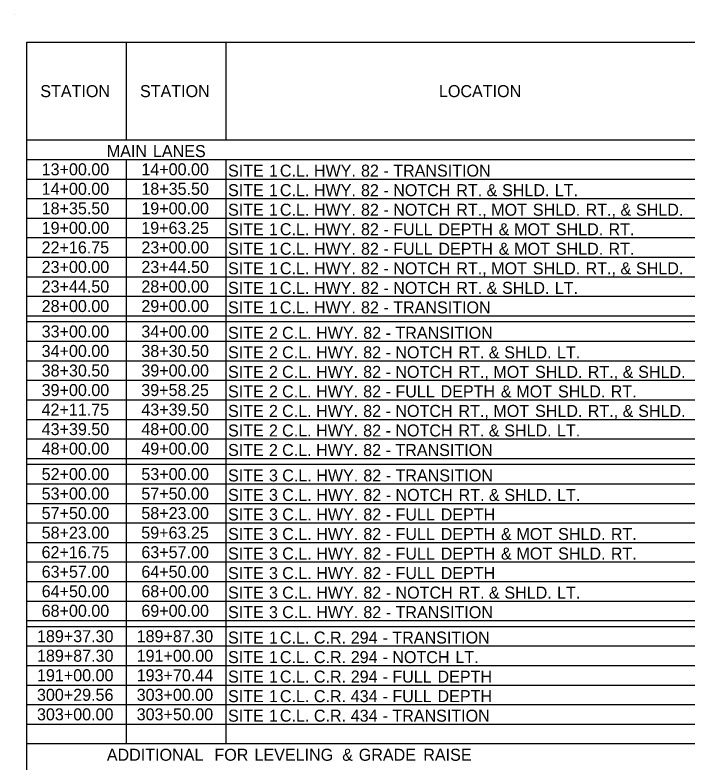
# Model space of a CAD drawing. Extents: x 977434 to 989596, y 1525697 to 1528336.
# Drawn here: x 982700.1 to 982968.2, y 1527813.7 to 1528112 of the extents above; entities that cross this region are included whole.
import ezdxf

# ---------------------------------------------------------------- set-up
doc = ezdxf.new("R2010")
doc.units = 0
doc.layers.add('Default', color=7, linetype='Continuous')
doc.layers.add('R_Border Prem', color=7, linetype='Continuous')

msp = doc.modelspace()

# ---------------------------------------------------------------- linework, layer by layer
at = {"layer": 'Default'}
for p, q in [((982704.74, 1528101.06), (984062.72, 1528101.06)), ((982704.74, 1527610.44), (982704.74, 1528101.06)), ((982704.74, 1527610.44), (982704.74, 1528101.06)), ((982744.52, 1528062.06), (982744.52, 1528101.06)), ((982784.3, 1528062.06), (982784.3, 1528101.06)), ((982704.74, 1528062.06), (984062.72, 1528062.06)), ((982704.74, 1528054.26), (984062.72, 1528054.26)), ((982744.52, 1527821.04), (982744.52, 1528054.26)), ((982744.52, 1527821.04), (982744.52, 1528054.26)), ((982784.3, 1527821.04), (982784.3, 1528054.26)), ((982784.3, 1527821.04), (982784.3, 1528054.26)), ((982704.74, 1528046.46), (984062.72, 1528046.46)), ((982704.74, 1528038.66), (984062.72, 1528038.66)), ((982704.74, 1528030.86), (984062.72, 1528030.86)), ((982704.74, 1528023.06), (984062.72, 1528023.06)), ((982704.74, 1528015.26), (984062.72, 1528015.26)), ((982704.74, 1528007.46), (984062.72, 1528007.46)), ((982704.74, 1527999.66), (984062.72, 1527999.66)), ((982704.74, 1527991.86), (984062.72, 1527991.86)), ((982704.74, 1527989.52), (984062.72, 1527989.52)), ((982704.74, 1527981.72), (984062.72, 1527981.72)), ((982704.74, 1527973.92), (984062.72, 1527973.92)), ((982704.74, 1527966.12), (984062.72, 1527966.12)), ((982704.74, 1527958.32), (984062.72, 1527958.32)), ((982704.74, 1527950.52), (984062.72, 1527950.52)), ((982704.74, 1527942.72), (984062.72, 1527942.72)), ((982704.74, 1527934.92), (984062.72, 1527934.92)), ((982704.74, 1527932.58), (984062.72, 1527932.58)), ((982704.74, 1527924.78), (984062.72, 1527924.78)), ((982704.74, 1527916.98), (984062.72, 1527916.98)), ((982704.74, 1527909.18), (984062.72, 1527909.18)), ((982704.74, 1527901.38), (984062.72, 1527901.38)), ((982704.74, 1527893.58), (984062.72, 1527893.58)), ((982704.74, 1527885.78), (984062.72, 1527885.78)), ((982704.74, 1527877.98), (984062.72, 1527877.98)), ((982704.74, 1527870.18), (984062.72, 1527870.18)), ((982704.74, 1527867.84), (984062.72, 1527867.84)), ((982704.74, 1527860.04), (984062.72, 1527860.04)), ((982704.74, 1527852.24), (984062.72, 1527852.24)), ((982704.74, 1527844.44), (984062.72, 1527844.44)), ((982704.74, 1527836.64), (984062.72, 1527836.64)), ((982704.74, 1527828.84), (984062.72, 1527828.84)), ((982704.74, 1527821.04), (983147.78, 1527821.04)), ((982704.74, 1527821.04), (984062.72, 1527821.04))]:
    msp.add_line(p, q, dxfattribs=at)
at = {"layer": 'R_Border Prem'}
msp.add_line((982700.06, 1528111.98), (982700.06, 1528111.98), dxfattribs=at)

# ---------------------------------------------------------------- texts
at = {"layer": 'Default'}
for s, p in [('STATION', (982710.18, 1528079.16)), ('STATION', (982749.96, 1528079.16)), ('LOCATION', (982869.24, 1528079.16)), ('MAIN', (982736.72, 1528055.22)), (' LANES', (982753.32, 1528055.22)), ('13+00.00', (982710.72, 1528047.96)), ('14+00.00', (982750.5, 1528047.96)), ('SITE', (982785.08, 1528047.42)), (' 1', (982799.63, 1528047.42)), (' C.L.', (982803.99, 1528047.42)), (' HWY.', (982817.56, 1528047.42)), (' 82', (982836.35, 1528047.42)), (' TRANSITION', (982849.2, 1528047.42)), (' -', (982845.31, 1528047.42)), ('14+00.00', (982710.72, 1528040.16)), ('18+35.50', (982750.5, 1528040.16)), ('SITE', (982785.08, 1528039.62)), (' 1', (982799.63, 1528039.62)), (' C.L.', (982803.99, 1528039.62)), (' HWY.', (982817.56, 1528039.62)), (' 82', (982836.35, 1528039.62)), (' NOTCH', (982849.2, 1528039.62)), (' RT.', (982874.36, 1528039.62)), (' &', (982886.44, 1528039.62)), (' SHLD.', (982892.63, 1528039.62)), (' LT.', (982913.66, 1528039.62)), (' -', (982845.31, 1528039.62)), ('18+35.50', (982710.72, 1528032.36)), ('19+00.00', (982750.5, 1528032.36)), ('SITE', (982785.08, 1528031.82)), (' 1', (982799.63, 1528031.82)), (' C.L.', (982803.99, 1528031.82)), (' HWY.', (982817.56, 1528031.82)), (' 82', (982836.35, 1528031.82)), (' NOTCH', (982849.2, 1528031.82)), (' RT.,', (982874.36, 1528031.82)), (' MOT', (982888.29, 1528031.82)), (' SHLD.', (982904.92, 1528031.82)), (' RT.,', (982925.95, 1528031.82)), (' &', (982939.88, 1528031.82)), (' SHLD.', (982946.07, 1528031.82)), (' -', (982845.31, 1528031.82)), ('19+00.00', (982710.72, 1528024.56)), ('19+63.25', (982750.47, 1528024.56)), ('SITE', (982785.08, 1528024.02)), (' 1', (982799.63, 1528024.02)), (' C.L.', (982803.99, 1528024.02)), (' HWY.', (982817.56, 1528024.02)), (' 82', (982836.35, 1528024.02)), (' FULL', (982849.2, 1528024.02)), (' DEPTH', (982867.22, 1528024.02)), (' &', (982891.27, 1528024.02)), (' MOT', (982897.46, 1528024.02)), (' SHLD.', (982914.08, 1528024.02)), (' RT.', (982935.11, 1528024.02)), (' -', (982845.31, 1528024.02)), ('22+16.75', (982710.69, 1528016.76)), ('23+00.00', (982750.5, 1528016.76)), ('SITE', (982785.08, 1528016.22)), (' 1', (982799.63, 1528016.22)), (' C.L.', (982803.99, 1528016.22)), (' HWY.', (982817.56, 1528016.22)), (' 82', (982836.35, 1528016.22)), (' FULL', (982849.2, 1528016.22)), (' DEPTH', (982867.22, 1528016.22)), (' &', (982891.27, 1528016.22)), (' MOT', (982897.46, 1528016.22)), (' SHLD.', (982914.08, 1528016.22)), (' RT.', (982935.11, 1528016.22)), (' -', (982845.31, 1528016.22)), ('23+00.00', (982710.72, 1528008.96)), ('23+44.50', (982750.5, 1528008.96)), ('SITE', (982785.08, 1528008.42)), (' 1', (982799.63, 1528008.42)), (' C.L.', (982803.99, 1528008.42)), (' HWY.', (982817.56, 1528008.42)), (' 82', (982836.35, 1528008.42)), (' NOTCH', (982849.2, 1528008.42)), (' RT.,', (982874.36, 1528008.42)), (' MOT', (982888.29, 1528008.42)), (' SHLD.', (982904.92, 1528008.42)), (' RT.,', (982925.95, 1528008.42)), (' &', (982939.88, 1528008.42)), (' SHLD.', (982946.07, 1528008.42)), (' -', (982845.31, 1528008.42)), ('23+44.50', (982710.72, 1528001.16)), ('28+00.00', (982750.5, 1528001.16)), ('SITE', (982785.08, 1528000.62)), (' 1', (982799.63, 1528000.62)), (' C.L.', (982803.99, 1528000.62)), (' HWY.', (982817.56, 1528000.62)), (' 82', (982836.35, 1528000.62)), (' NOTCH', (982849.2, 1528000.62)), (' RT.', (982874.36, 1528000.62)), (' &', (982886.44, 1528000.62)), (' SHLD.', (982892.63, 1528000.62)), (' LT.', (982913.66, 1528000.62)), (' -', (982845.31, 1528000.62)), ('28+00.00', (982710.72, 1527993.36)), ('29+00.00', (982750.5, 1527993.36)), ('SITE', (982785.08, 1527992.82)), (' 1', (982799.63, 1527992.82)), (' C.L.', (982803.99, 1527992.82)), (' HWY.', (982817.56, 1527992.82)), (' 82', (982836.35, 1527992.82)), (' TRANSITION', (982849.2, 1527992.82)), (' -', (982845.31, 1527992.82)), ('33+00.00', (982710.72, 1527983.22)), ('34+00.00', (982750.5, 1527983.22)), ('SITE', (982785.08, 1527982.68)), (' 2', (982799.63, 1527982.68)), (' C.L.', (982804.87, 1527982.68)), (' 82', (982837.22, 1527982.68)), (' TRANSITION', (982850.07, 1527982.68)), (' HWY.', (982818.44, 1527982.68)), (' -', (982846.19, 1527982.68)), ('34+00.00', (982710.72, 1527975.42)), ('38+30.50', (982750.5, 1527975.42)), ('SITE', (982785.08, 1527974.88)), (' 2', (982799.63, 1527974.88)), (' C.L.', (982804.87, 1527974.88)), (' HWY.', (982818.44, 1527974.88)), (' 82', (982837.22, 1527974.88)), (' NOTCH', (982850.07, 1527974.88)), (' RT.', (982875.24, 1527974.88)), (' &', (982887.32, 1527974.88)), (' SHLD.', (982893.5, 1527974.88)), (' LT.', (982914.53, 1527974.88)), (' -', (982846.19, 1527974.88)), ('38+30.50', (982710.72, 1527967.62)), ('39+00.00', (982750.5, 1527967.62)), ('SITE', (982785.08, 1527967.08)), (' 2', (982799.63, 1527967.08)), (' C.L.', (982804.87, 1527967.08)), (' HWY.', (982818.44, 1527967.08)), (' 82', (982837.22, 1527967.08)), (' NOTCH', (982850.07, 1527967.08)), (' RT.,', (982875.24, 1527967.08)), (' MOT', (982889.17, 1527967.08)), (' SHLD.', (982905.8, 1527967.08)), (' RT.,', (982926.83, 1527967.08)), (' &', (982940.76, 1527967.08)), (' SHLD.', (982946.94, 1527967.08)), (' -', (982846.19, 1527967.08)), ('39+00.00', (982710.72, 1527959.82)), ('39+58.25', (982750.47, 1527959.82)), ('SITE', (982785.08, 1527959.28)), (' 2', (982799.63, 1527959.28)), (' C.L.', (982804.87, 1527959.28)), (' HWY.', (982818.44, 1527959.28)), (' 82', (982837.22, 1527959.28)), (' FULL', (982850.07, 1527959.28)), (' DEPTH', (982868.1, 1527959.28)), (' &', (982892.15, 1527959.28)), (' MOT', (982898.33, 1527959.28)), (' SHLD.', (982914.96, 1527959.28)), (' RT.', (982935.99, 1527959.28)), (' -', (982846.19, 1527959.28)), ('42+11.75', (982710.69, 1527952.02)), ('43+39.50', (982750.5, 1527952.02)), ('SITE', (982785.08, 1527951.48)), (' 2', (982799.63, 1527951.48)), (' C.L.', (982804.87, 1527951.48)), (' HWY.', (982818.44, 1527951.48)), (' 82', (982837.22, 1527951.48)), (' NOTCH', (982850.07, 1527951.48)), (' RT.,', (982875.24, 1527951.48)), (' MOT', (982889.17, 1527951.48)), (' SHLD.', (982905.8, 1527951.48)), (' RT.,', (982926.83, 1527951.48)), (' &', (982940.76, 1527951.48)), (' SHLD.', (982946.94, 1527951.48)), (' -', (982846.19, 1527951.48)), ('43+39.50', (982710.72, 1527944.22)), ('48+00.00', (982750.5, 1527944.22)), ('SITE', (982785.08, 1527943.68)), (' 2', (982799.63, 1527943.68)), (' C.L.', (982804.87, 1527943.68)), (' HWY.', (982818.44, 1527943.68)), (' 82', (982837.22, 1527943.68)), (' -', (982846.19, 1527943.68)), (' NOTCH', (982850.07, 1527943.68)), (' RT.', (982875.24, 1527943.68)), (' &', (982887.32, 1527943.68)), (' SHLD.', (982893.5, 1527943.68)), (' LT.', (982914.53, 1527943.68)), ('48+00.00', (982710.72, 1527936.42)), ('49+00.00', (982750.5, 1527936.42)), ('SITE', (982785.08, 1527935.88)), (' 2', (982799.63, 1527935.88)), (' C.L.', (982804.87, 1527935.88)), (' HWY.', (982818.44, 1527935.88)), (' 82', (982837.22, 1527935.88)), (' TRANSITION', (982850.07, 1527935.88)), (' -', (982846.19, 1527935.88)), ('52+00.00', (982710.72, 1527926.28)), ('53+00.00', (982750.5, 1527926.28)), ('SITE', (982785.08, 1527925.74)), (' 3', (982799.63, 1527925.74)), (' C.L.', (982804.92, 1527925.74)), (' HWY.', (982818.49, 1527925.74)), (' 82', (982837.28, 1527925.74)), (' -', (982846.24, 1527925.74)), (' TRANSITION', (982850.12, 1527925.74)), ('53+00.00', (982710.72, 1527918.48)), ('57+50.00', (982750.5, 1527918.48)), ('SITE', (982785.08, 1527917.94)), (' 3', (982799.63, 1527917.94)), (' C.L.', (982804.92, 1527917.94)), (' HWY.', (982818.49, 1527917.94)), (' 82', (982837.28, 1527917.94)), (' NOTCH', (982850.12, 1527917.94)), (' RT.', (982875.29, 1527917.94)), (' &', (982887.37, 1527917.94)), (' SHLD.', (982893.56, 1527917.94)), (' LT.', (982914.58, 1527917.94)), (' -', (982846.24, 1527917.94)), ('57+50.00', (982710.72, 1527910.68)), ('58+23.00', (982750.5, 1527910.68)), ('SITE', (982785.08, 1527910.14)), (' 3', (982799.63, 1527910.14)), (' C.L.', (982804.92, 1527910.14)), (' HWY.', (982818.49, 1527910.14)), (' 82', (982837.28, 1527910.14)), (' FULL', (982850.12, 1527910.14)), (' DEPTH', (982868.15, 1527910.14)), (' -', (982846.24, 1527910.14)), ('58+23.00', (982710.72, 1527902.88)), ('59+63.25', (982750.47, 1527902.88)), ('SITE', (982785.08, 1527902.34)), (' 3', (982799.63, 1527902.34)), (' C.L.', (982804.92, 1527902.34)), (' HWY.', (982818.49, 1527902.34)), (' 82', (982837.28, 1527902.34)), (' FULL', (982850.12, 1527902.34)), (' DEPTH', (982868.15, 1527902.34)), (' &', (982892.2, 1527902.34)), (' MOT', (982898.38, 1527902.34)), (' SHLD.', (982915.01, 1527902.34)), (' RT.', (982936.04, 1527902.34)), (' -', (982846.24, 1527902.34)), ('62+16.75', (982710.69, 1527895.08)), ('63+57.00', (982750.5, 1527895.08)), ('SITE', (982785.08, 1527894.54)), (' 3', (982799.63, 1527894.54)), (' C.L.', (982804.92, 1527894.54)), (' HWY.', (982818.49, 1527894.54)), (' 82', (982837.28, 1527894.54)), (' FULL', (982850.12, 1527894.54)), (' DEPTH', (982868.15, 1527894.54)), (' &', (982892.2, 1527894.54)), (' MOT', (982898.38, 1527894.54)), (' SHLD.', (982915.01, 1527894.54)), (' RT.', (982936.04, 1527894.54)), (' -', (982846.24, 1527894.54)), ('63+57.00', (982710.72, 1527887.28)), ('64+50.00', (982750.5, 1527887.28)), ('SITE', (982785.08, 1527886.74)), (' 3', (982799.63, 1527886.74)), (' C.L.', (982804.92, 1527886.74)), (' HWY.', (982818.49, 1527886.74)), (' 82', (982837.28, 1527886.74)), (' FULL', (982850.12, 1527886.74)), (' DEPTH', (982868.15, 1527886.74)), (' -', (982846.24, 1527886.74)), ('64+50.00', (982710.72, 1527879.48)), ('68+00.00', (982750.5, 1527879.48)), ('SITE', (982785.08, 1527878.94)), (' 3', (982799.63, 1527878.94)), (' C.L.', (982804.92, 1527878.94)), (' HWY.', (982818.49, 1527878.94)), (' 82', (982837.28, 1527878.94)), (' NOTCH', (982850.12, 1527878.94)), (' RT.', (982875.29, 1527878.94)), (' &', (982887.37, 1527878.94)), (' SHLD.', (982893.56, 1527878.94)), (' LT.', (982914.58, 1527878.94)), (' -', (982846.24, 1527878.94)), ('68+00.00', (982710.72, 1527871.68)), ('69+00.00', (982750.5, 1527871.68)), ('SITE', (982785.08, 1527871.14)), (' 3', (982799.63, 1527871.14)), (' C.L.', (982804.92, 1527871.14)), (' HWY.', (982818.49, 1527871.14)), (' 82', (982837.28, 1527871.14)), (' TRANSITION', (982850.12, 1527871.14)), (' -', (982846.24, 1527871.14)), ('189+37.30', (982708.85, 1527861.54)), ('189+87.30', (982748.63, 1527861.54)), ('SITE', (982785.08, 1527861)), (' 1', (982799.63, 1527861)), (' C.L.', (982803.99, 1527861)), (' C.R.', (982817.56, 1527861)), (' 294', (982832.25, 1527861)), (' TRANSITION', (982848.86, 1527861)), (' -', (982844.97, 1527861)), ('189+87.30', (982708.85, 1527853.74)), ('191+00.00', (982748.63, 1527853.74)), ('SITE', (982785.08, 1527853.2)), (' 1', (982799.63, 1527853.2)), (' C.L.', (982803.99, 1527853.2)), (' C.R.', (982817.56, 1527853.2)), (' 294', (982832.25, 1527853.2)), (' NOTCH', (982848.86, 1527853.2)), (' LT.', (982874.02, 1527853.2)), (' -', (982844.97, 1527853.2)), ('191+00.00', (982708.85, 1527845.94)), ('193+70.44', (982748.64, 1527845.94)), ('SITE', (982785.08, 1527845.4)), (' 1', (982799.63, 1527845.4)), (' C.L.', (982803.99, 1527845.4)), (' C.R.', (982817.56, 1527845.4)), (' 294', (982832.25, 1527845.4)), (' -', (982844.97, 1527845.4)), (' FULL', (982848.86, 1527845.4)), (' DEPTH', (982866.88, 1527845.4)), ('300+29.56', (982708.84, 1527838.14)), ('303+00.00', (982748.63, 1527838.14)), ('SITE', (982785.08, 1527837.6)), (' 1', (982799.63, 1527837.6)), (' C.L.', (982803.99, 1527837.6)), (' C.R.', (982817.56, 1527837.6)), (' 434', (982832.25, 1527837.6)), (' FULL', (982848.86, 1527837.6)), (' DEPTH', (982866.88, 1527837.6)), (' -', (982844.97, 1527837.6)), ('303+00.00', (982708.85, 1527830.34)), ('303+50.00', (982748.63, 1527830.34)), ('SITE', (982785.08, 1527829.8)), (' 1', (982799.63, 1527829.8)), (' C.L.', (982803.99, 1527829.8)), (' C.R.', (982817.56, 1527829.8)), (' 434', (982832.25, 1527829.8)), (' TRANSITION', (982848.86, 1527829.8)), (' -', (982844.97, 1527829.8)), ('ADDITIONAL', (982736.72, 1527814.2)), (' FOR', (982777.87, 1527814.2)), (' LEVELING', (982793.86, 1527814.2)), (' &', (982828.86, 1527814.2)), (' GRADE', (982835.46, 1527814.2)), (' RAISE', (982861.21, 1527814.2))]:
    msp.add_text(s, height=4.8, dxfattribs=at).set_placement(p)

doc.saveas('drawing.dxf')
